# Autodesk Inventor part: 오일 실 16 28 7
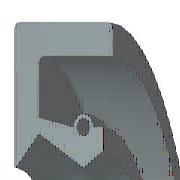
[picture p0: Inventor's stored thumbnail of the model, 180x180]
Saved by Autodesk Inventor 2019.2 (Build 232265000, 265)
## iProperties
Created: 2012-02
Part Number: 오일 실 16 28 7
Material: 고무
Description: 오일-실
Document SubType Name: Modeling
Standard: KS B 2804
Designer: mduedu
Standards Organization: KS
Language: ko-KR
Size Designation: D - 16 28 7
Categories: <MemberInstance><Categories><Category DisplayName="샤프트 부품" InternalName="7f7aeb1f-a693-4053-b835-cee3144e0d98" Mnemonic="SHFT"><Category DisplayName="실링" Intern
Density: 0.93 g/cm^3
Appearance: 고무 - 검은색 - 버전 1.1
IsCustomPart: 1
Author: mduedu
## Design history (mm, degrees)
revolve "본체" stored, may be unused: angle "d17" = 90 deg
revolve "스프링1" stored, may be unused: angle "d18" = 90 deg
fillet "모깎기3" dims "d43" = 0.5
body "Solid1"
sketch "스케치1"
  geometry: L1 (0, 14)-(7, 14); L2 (7, 12.25)-(1.75, 12.25); L3 (1.75, 9.75)-(4.9, 8); L4 (4.9, 8)-(0, 8); L5 (0, 0)-(9.586, 0) reference; L6 (4.9, 8)-(6.3, 8.875); L7 (0, 18)-(0, -3) reference; L8 (-1.941, 0)-(11.507, 0) reference; L9 (4.2, 10.1)-(1.75, 10.59); L10 (1.75, 10.59)-(1.75, 12.25); L11 (0, 14)-(0, 8.088); L12 (4.9, 8)-(0, 8); L13 (1.75, 9.75)-(0.152, 8.028); L14 (7, 14)-(7, 12.25); L15 (5.6, 10.1)-(6.3, 10.1); L16 (6.3, 10.1)-(6.3, 8.875); C1 r 0.455 at (4.9, 10.1); A1 r 0.7 centre (4.9, 10.1) between (5.6, 10.1) and (4.2, 10.1); A2 r 0.088 centre (0.088, 8.088) between (0, 8.088) and (0.152, 8.028); 1 further point
  constraints: 28 end point, 5 horizontal alignment, 5 point on line, 4 point on circle, 4 vertical alignment, 3 centre point, 3 tangent, 2 collinear, 2 horizontal, 2 perpendicular, 1 coincident, 1 parallel
  dimensions: "d0" = 28 diameter of L1 L5 (= SD2); "d1" = 1.75 distance of L1.end L2.start (= SD); "d2" = 0.91 diameter of C1 (= SPDI); "d3" = 1.4 diameter of A1 (= SPDA); "d4" = 16 diameter of L3.end L5 (= NND); "d5" = 19.5 diameter of L3.start L5 (= TKDM); "d7" = 21.18 diameter of L9.end L5 (= TKDM + 0.24 x SWDT); "d8" = 1.75 distance between parallel lines of L11 L10 (= SD); "d9" = 4.9 distance from line of L11 C1.centre (= SPDST); "d10" = 20.2 diameter of C1.centre L5 (= HLDM); "d11" = 0.0875 radius of A2 (= 0.25 x LAB); "d12" = 6.3 distance between parallel lines of L11 L16 (= SDI); "d13" = 17.75 diameter of L6.end L5 (= ABDM); "d14" = 7 distance from line of L11 L1.end (= SWDT)
fillet "모깎기1" dims "d6" = 0.3 (= RR)
other parameters: "SD2" = 28 [user parameter; used in 1 equation term], "SWDT" = 7 [user parameter; used in 2 equation terms], "RR" = 0.3 [user parameter; used in 1 equation term], "SD" = 1.75 [user parameter; used in 2 equation terms], "NND" = 16 [user parameter; used in 1 equation term], "SPDA" = 1.4 [user parameter; used in 1 equation term], "SPDI" = 0.91 [user parameter; used in 1 equation term], "TKDM" = 19.5 [user parameter; used in 2 equation terms], "HLDM" = 20.2 [user parameter; used in 1 equation term], "ABDM" = 17.75 [user parameter; used in 1 equation term], "SDI" = 6.3 [user parameter; used in 1 equation term], "SPDST" = 4.9 [user parameter; used in 1 equation term], "LAB" = 0.35 [user parameter; used in 1 equation term], "d15" = 0, "d16" = 0, "d19" = 0
